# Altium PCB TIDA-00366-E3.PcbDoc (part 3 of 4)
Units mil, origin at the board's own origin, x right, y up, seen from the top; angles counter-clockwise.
Board outline 6298.95 x 6141.73 mil, 4 copper layers (Top Layer, GND, PWR, Bottom Layer), stack 79.834 mil thick; 362 components, 168 nets, 919 pads, 271 vias.
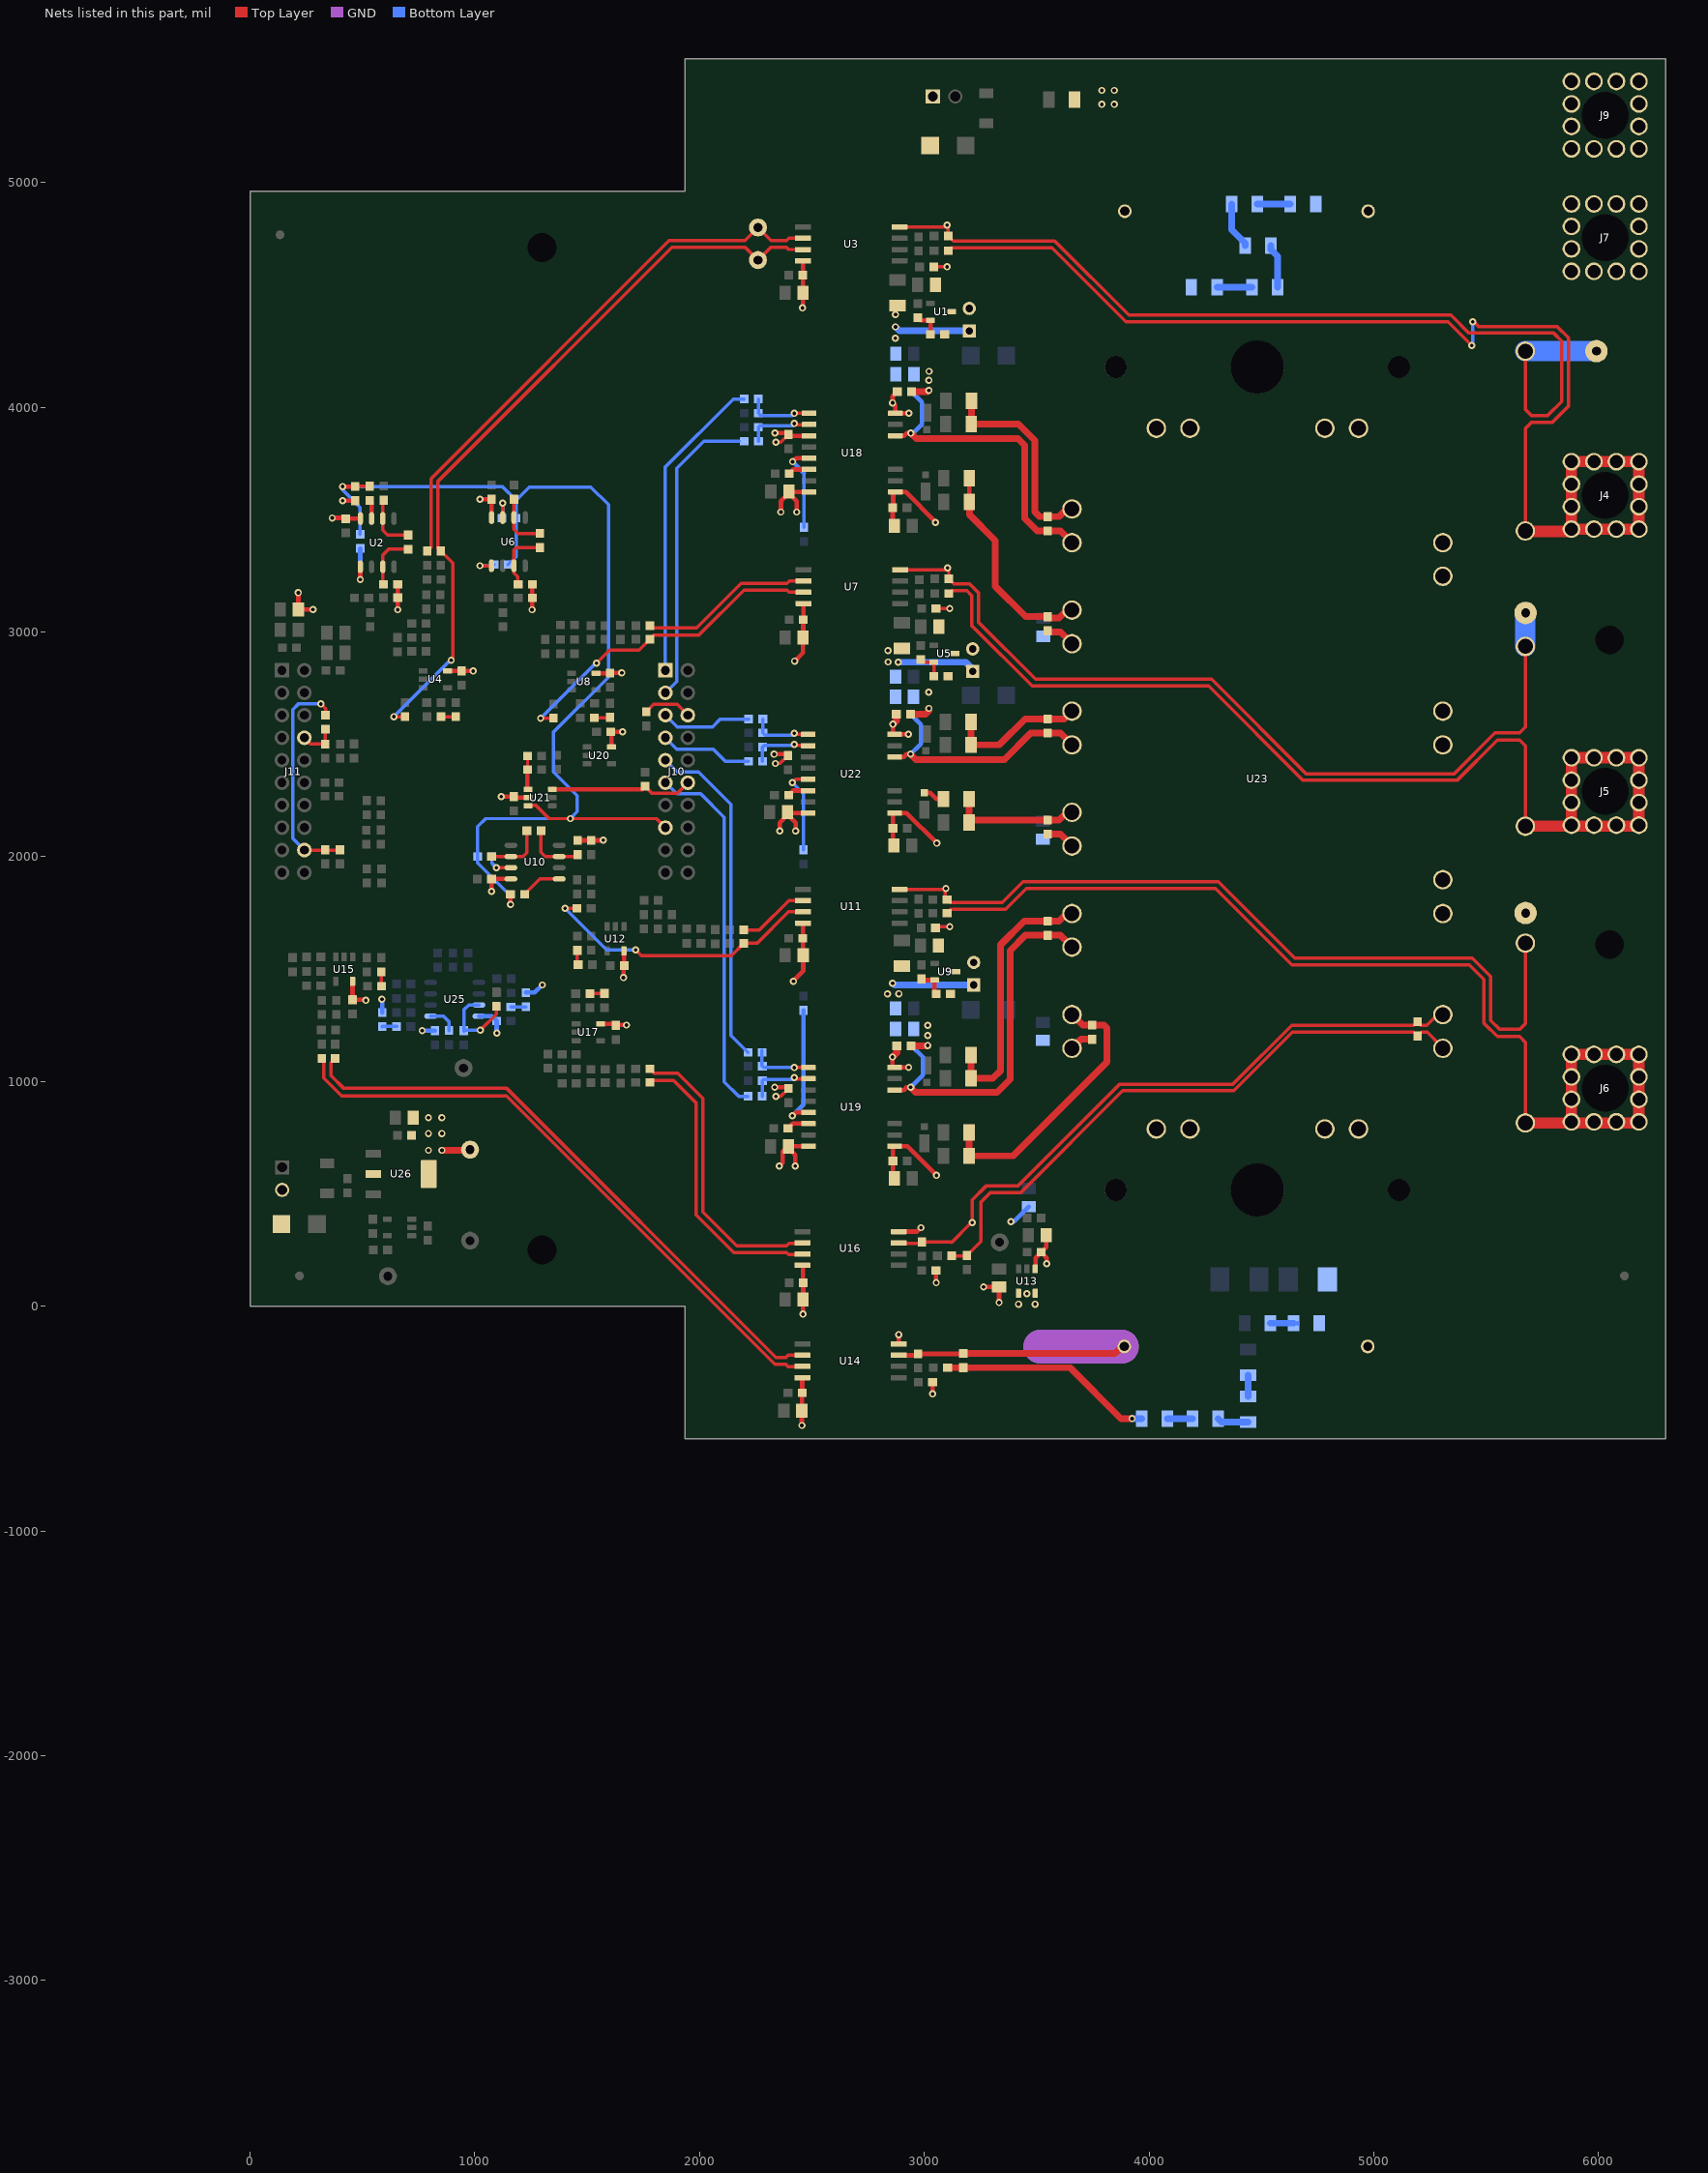
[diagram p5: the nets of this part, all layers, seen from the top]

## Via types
v1: diameter 32, hole 16, Top Layer to Bottom Layer, 271 vias

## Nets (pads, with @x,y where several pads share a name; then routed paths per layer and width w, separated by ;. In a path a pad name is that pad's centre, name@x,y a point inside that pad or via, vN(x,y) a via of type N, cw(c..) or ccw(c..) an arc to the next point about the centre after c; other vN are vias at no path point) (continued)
NetD11_2: D11.2 R130.1 | length 96.4
  Top Layer w20: D11.2@3000,2284.21 3025.79,2284.21 3053.55,2256.45 R130.1@3084.9,2256.45
NetD12_2: D12.2 J8.1
NetD13_2: D13.2 J12.2
NetJ10_1: J10.1 R143.2 | length 1380.6
  Bottom Layer w15: J10.1@1847.73,2829.45 1847.73,3734.45 2149.73,4036.45 R143.2@2198.24,4036.45
NetJ10_3: J10.3 R145.2 | length 1347.9
  Bottom Layer w15: J10.3@1847.73,2729.45 1897.73,2779.45 1897.73,3727.45 2019.28,3848.99 2176.55,3848.99
NetJ10_5: J10.5 R150.2 | length 406.5
  Bottom Layer w15: J10.5@1847.73,2629.45 1899.73,2577.45 2057.73,2577.45 2092.73,2612.45 R150.2@2218.24,2612.45
NetJ10_6: J10.6 R147.2 | length 218.2
  Top Layer w15: R147.2@1763,2644.5 1795.93,2677.43 1899.75,2677.43 J10.6@1947.73,2629.45
NetJ10_7: J10.7 R152.2 | length 413
  Bottom Layer w15: J10.7@1847.73,2529.45 1898.73,2478.45 2060.73,2478.45 2114.73,2424.45 R152.2@2217.24,2424.45
NetJ10_9: J10.9 R153.2 | length 1507.9
  Bottom Layer w15: J10.9@1847.73,2429.45 1899.73,2377.45 1994.73,2377.45 2139.73,2232.45 2139.73,1204.95 R153.2@2215.24,1129.45
NetJ10_11: J10.11 R156.2 | length 1634.5
  Bottom Layer w15: J10.11@1847.73,2329.45 1897.73,2279.45 2004.73,2279.45 2109.73,2174.45 2109.73,997.99 2173.28,934.45 R156.2@2215.24,934.45
NetJ11_8: J11.8 R148.1 R149.1 | length 171.2
  Top Layer w15: J11.8@241.73,2529.45 270.24,2500.95 R148.1@334.73,2500.95 334.73,2565.95 R149.1@335.73,2566.95
NetR2_1: R2.1 R6.2 U1.2 | length 124
  Top Layer w20: R6.2@2970.73,4397.95 2981.64,4387.05 U1.2@3027.49,4387.05 3027.49,4324.7 R2.1@3027.24,4324.45
NetR3_1: R3.1 U2.1 | length 196.5
  Top Layer w20: v1(490.19,3232.82) 490.19,3289.73 U2.1@490.51,3290.06
  Bottom Layer w20: R3.1@490,3371.5 490.51,3370.99 490.19,3370.67 490.19,3290.06 ; v1(490.19,3232.82) 490.51,3233.14 490.51,3290.06
NetR4_1: R4.1 R11.2 U2.3 | length 254.3
  Top Layer w15: R4.1@594.02,3212.34 590.51,3215.84 U2.3@590.51,3290.06 590.51,3341.84 616.59,3367.92 R11.2@703.09,3367.92
NetR7_2: R7.2 R8.1 | length 64.7
  Top Layer w15: R8.1@850.23,2623.45 850.73,2622.95 R7.2@914.73,2622.95
NetR11_1: R11.1 R19.2 U2.6 | length 256.7
  Top Layer w15: R19.2@594.09,3585.92 590.51,3582.35 U2.6@590.51,3504.62 590.51,3451.99 611.59,3430.91 R11.1@703.09,3430.91
NetR15_1: R15.1 TP2.1 U3.6 | length 2475.1
  Top Layer w15: R15.1@788.61,3359.95 804.73,3376.07 804.73,3681.73 1864.45,4741.45 2201.73,4741.45 TP2.1@2259.73,4799.45 2317.73,4741.45 2386.73,4741.45 2396.86,4751.58 U3.6@2460.17,4751.58
NetR20_1: R20.1 U2.7 | length 84.4
  Top Layer w20: R20.1@532,3585.5 540.51,3576.99 U2.7@540.51,3504.62
NetR23_1: R23.1 R27.2 U5.2 | length 125.2
  Top Layer w15: R27.2@2983.73,2876.95 2994.64,2866.05 U5.2@3041.49,2866.05 3042.24,2865.3 R23.1@3042.24,2803.45
NetR24_1: R24.1 U6.1 | length 117.1
  Top Layer w15: v1@1022.95,3294 v1(1022.47,3294.47) U6.1@1074.21,3294.47
  Bottom Layer w15: v1@1022.95,3294 1079.42,3294 R24.1@1085.24,3299.82
NetR25_1: R25.1 R32.2 U6.3 | length 279.7
  Top Layer w15: R25.1@1192.72,3211.76 1190.08,3214.4 1190.08,3246.84 1174.21,3262.7 U6.3@1174.21,3294.47 1174.21,3364.26 1185.21,3375.26 R32.2@1289.21,3375.26
NetR28_2: R28.2 R29.1 | length 69.9
  Top Layer w15: R29.1@1531.76,2618.32 1599.51,2618.32 R28.2@1601.04,2619.84
NetR32_1: R32.1 R40.2 U6.6 | length 256.4
  Top Layer w15: R40.2@1174.21,3590.26 U6.6@1174.21,3509.04 1174.21,3456.41 1192.37,3438.25 R32.1@1289.21,3438.25
NetR36_1: R36.1 U7.6 | length 773.3
  Top Layer w15: R36.1@1779.25,3027.99 1788.79,3018.45 1987.31,3018.45 2185.05,3216.2 2389.08,3216.2 2399.21,3226.32 U7.6@2462.51,3226.32
NetR41_1: R41.1 U6.7 | length 131.5
  Top Layer w15: v1@1124,3573 v1(1124.21,3572.79) U6.7@1124.21,3509.04
  Bottom Layer w15: R41.1@1120.5,3507 1124,3510.5 v1@1124,3573
NetR44_1: R44.1 R48.2 U9.2 | length 125.6
  Top Layer w20: R48.2@2986.73,1455.95 2991.64,1451.05 U9.2@3045.49,1451.05 3045.49,1397.2 R44.1@3053.24,1389.45
NetR45_1: R45.1 U10.1 | length 181.8
  Top Layer w15: R45.1@1221.5,1833 1289.4,1900.91 U10.1@1375.17,1900.91
NetR46_1: R46.1 R53.2 U10.3 | length 270.6
  Top Layer w15: R53.2@1294.38,2115.91 1294.38,2020.48 1313.96,2000.91 U10.3@1375.17,2000.91 1449.38,2000.91 R46.1@1457.88,2009.41
NetR49_2: R49.2 R50.1 | length 65
  Top Layer w15: R50.1@1455.96,1583.41 1455.96,1523.41 R49.2@1459.46,1519.91
NetR53_1: R53.1 R61.2 U10.6 | length 261.8
  Top Layer w15: R61.2@1074.38,2000.91 U10.6@1160.6,2000.91 1213.92,2000.91 1231.39,2018.38 R53.1@1231.39,2115.91
NetR57_1: R57.1 U11.6 | length 317.8
  Top Layer w15: R57.1@2196.23,1674.45 2266.86,1674.45 2396.86,1804.45 U11.6@2460.17,1804.45
NetR62_1: R62.1 U10.7 | length 101.4
  Top Layer w15: v1(1096,1951) 1096.09,1950.91 U10.7@1160.6,1950.91
  Bottom Layer w15: 1075.5,1979.3 1075.5,1971.5 v1(1096,1951)
NetR65_1: R65.1 R66.2 | length 105.2
  Bottom Layer w20: R65.1@4659.73,-75.55 R65.1@4660.73,-76.55
  Bottom Layer w30: R66.2@4538.82,-75.55 R65.1@4642.65,-75.55
NetR68_1: R68.1 R69.2 | length 94.8
  Bottom Layer w30: R69.2@4440.73,-401.46 R68.1@4440.73,-306.63
NetR69_1: R69.1 R70.2 | length 140.2
  Bottom Layer w30: R70.2@4306.82,-500.55 4321.9,-515.63 R69.1@4440.73,-515.63
NetR70_1: R70.1 R73.2 | length 110.8
  Bottom Layer w30: R73.2@4081.82,-500.55 R70.1@4192.65,-500.55
NetR71_2: R71.2 R72.1 | length 64.1
  Top Layer w15: R72.1@583.73,1487.91 583.73,1425.9 R71.2@585.23,1424.4
NetR73_1: R73.1 R74.1 R79.2 | length 958.9
  Top Layer w30: R74.1@3103.23,-273.55 3103.28,-273.5 R79.2@3173,-273.5 3647.68,-273.5 3874.73,-500.55 3875.28,-500 v1(3924,-500)
  Bottom Layer w30: v1(3924,-500) 3967.1,-500 R73.1@3967.65,-500.55
NetR75_1: R75.1 U14.6 | length 2705.8
  Top Layer w15: R75.1@378.73,1102.91 359.93,1084.11 359.93,1026 416.93,969 1142.06,969 2339.73,-228.68 2383.73,-228.68 2393.86,-218.55 U14.6@2457.17,-218.55
NetR80_1: R80.1 U14.7 | length 2752.6
  Top Layer w15: R80.1@318.73,1102.91 328.27,1093.36 328.27,1014.73 408,935 1141.06,935 2334.73,-258.68 2383.73,-258.68 2393.61,-268.55 U14.7@2457.17,-268.55
NetR87_2: R87.2 R88.1 | length 64.7
  Top Layer w15: R88.1@1512.03,1390.91 1576.04,1390.91 R87.2@1576.53,1391.4
NetR90_1: R90.1 U16.6 | length 1307.5
  Top Layer w15: R90.1@1778.28,1055.45 1797.08,1036.65 1902.53,1036.65 2014.73,924.45 2014.73,419.45 2164.86,269.32 2386.73,269.32 2396.86,279.45 U16.6@2460.17,279.45
NetR93_1: R93.1 U16.7 | length 1298.5
  Top Layer w15: R93.1@1778.28,995.45 1787.82,1004.99 1884.19,1004.99 1984.73,904.45 1984.73,407.02 2152.43,239.32 2386.73,239.32 2396.61,229.45 U16.7@2460.17,229.45
NetR102_1: R102.1 R103.2 U21.4 | length 151.2
  Top Layer w12: R102.1@1234.24,2448.23 R103.2@1234.24,2388.23 R103.2@1235.87,2386.6
  Top Layer w20: R103.2@1234.24,2388.23 1234.24,2303.03 U21.4@1236.87,2300.4
NetR110_2: R110.2 U18.5 | length 392.9
  Top Layer w20: v1(2413.73,3757.45) 2429.28,3773 U18.5@2487.07,3773
  Bottom Layer w15: R110.2@2464.73,3465.5 2464.73,3706.45
  Bottom Layer w20: v1(2413.73,3757.45) 2464.73,3706.45
NetR111_2: R111.2 U19.5 | length 571.8
  Top Layer w20: v1(2412.86,846.86) 2429,863 U19.5@2488,863
  Bottom Layer w20: v1(2412.86,846.86) 2462,896 R111.2@2462,1316.5
NetR112_2: R112.2 U18.6 | length 95.5
  Top Layer w20: R112.2@2399.23,3704.45 2417.78,3723 U18.6@2487.07,3723
NetR113_2: R113.2 U19.6 | length 103.8
  Top Layer w20: R113.2@2393.36,790.86 2415.36,812.86 2426.94,812.86 2427.08,813 U19.6@2488,813
NetR127_2: R127.2 U22.5 | length 398.8
  Top Layer w15: v1(2412.73,2329.45) 2427.73,2344.45 U22.5@2485.98,2344.45
  Bottom Layer w15: v1(2412.73,2329.45) 2462,2280.18 R127.2@2462,2030.5
NetR128_2: R128.2 U22.6 | length 98.5
  Top Layer w20: R128.2@2396.23,2273.45 2417.23,2294.45 U22.6@2485.98,2294.45
NetR134_2: R134.2 R135.1 | length 145.8
  Bottom Layer w30: R135.1@4481.82,4904.45 R134.2@4627.65,4904.45
NetR135_2: R135.2 R136.1 | length 209.9
  Bottom Layer w30: R135.2@4367.65,4904.45 4367.65,4789.69 4427.65,4729.69 R136.1@4427.65,4719.45
NetR136_2: R136.2 R137.1 | length 197.4
  Bottom Layer w30: R136.2@4541.82,4719.45 4541.82,4702.36 4571.82,4672.36 R137.1@4571.82,4534.45
NetR137_2: R137.2 R138.1 | length 155.8
  Bottom Layer w30: R138.1@4301.82,4534.45 R137.2@4457.65,4534.45
NetR154_2: R154.2 R155.1 | length 64.7
  Bottom Layer w15: R154.2@587.76,1243.95 588.25,1244.45 R155.1@652.26,1244.45
NetR159_1: R159.1 U25.1 | length 131.2
  Bottom Layer w15: U25.1@803.47,1290.45 860.55,1290.45 885,1266 R159.1@885,1226.5
NetR163_2: R163.2 R165.1 | length 67.7
  Bottom Layer w15: R165.1@1160.23,1331.99 1227.23,1331.99 R163.2@1227.73,1332.5
NetR164_1: R164.1 R167.2 U25.7 | length 382.1
  Top Layer w15: v1(1024,1228) 1095.73,1299.73 R167.2@1095.73,1335.23
  Bottom Layer w15: R164.1@950.73,1225.95 R164.1@952.76,1227.97 ; R164.1@952.76,1222.95 R164.1@952.76,1227.97 ; R164.1@952.79,1228 v1(1024,1228) ; U25.7@1018.04,1340.45 972.76,1340.45 952.76,1320.45 R164.1@952.76,1227.97
NTC: R77.2 R89.1 R129.2 U23.17 | length 2728.1
  Top Layer w15: R89.1@3121.23,224.45 3188.24,224.45 R129.2@3189.73,225.95 3251.23,287.45 3251.23,463.52 3292.16,504.45 3427.73,504.45 3882,958.72 4376.24,958.72 4636.98,1219.45 5177.05,1219.45 R77.2@5194,1202.5 5210.95,1219.45 5236.54,1219.45 U23.17@5295.54,1160.45
OVERLOAD: J10.15 R1.1 R3.2 R20.2 R24.2 R41.2 R45.2 R62.2 U21.6 | length 5019.6
  Top Layer w15: R1.1@468.27,3647.05 469.72,3648.5 R20.2@532,3648.5 ; U21.6@1235.87,2227.6 1272.4,2227.6 1330.55,2169.45 v1(1424.73,2169.45) 1807.73,2169.45 J10.15@1847.73,2129.45
  Top Layer w20: v1(411.76,3647.05) R1.1@468.27,3647.05 ; R45.2@1158.5,1833 1158.5,1787.7 v1(1159,1787.21)
  Bottom Layer w15: R3.2@490,3434.5 490,3554 411.76,3632.24 v1(411.76,3647.05) 1122.95,3647.05 1183.5,3586.5 ; R24.2@1148.23,3299.82 1183.5,3335.09 R41.2@1183.5,3507 1183.5,3586.5 ; v1(1159,1787.21) 1159,1826 1012.5,1972.5 R62.2@1012.5,2001 1012.5,2133.5 1048.45,2169.45 v1(1424.73,2169.45) 1456,2200.72 1456,2271 1350,2377 1350,2554.72 1594.73,2799.45 1594.73,3566.27 1516,3645 1242,3645 1183.5,3586.5
PWM_U_BOT: C96.1 R145.1 U18.2 | length 302.3
  Top Layer w15: v1@2418.61,3932.57 2428.73,3922.45 U18.2@2486.98,3922.45
  Bottom Layer w15: R145.1@2262.23,3848.99 2261.23,3849.99 C96.1@2261.23,3910.99 2268.69,3918.45 2412.73,3918.45 v1(2421.73,3927.45)
PWM_U_TOP: C91.1 R143.1 U18.1 | length 296.3
  Top Layer w15: v1(2421.73,3972.45) U18.1@2486.98,3972.45
  Bottom Layer w15: R143.1@2261.23,4036.45 C91.1@2261.23,3973.99 2271.77,3963.45 2412.73,3963.45 v1(2421.73,3972.45)
PWM_V_BOT: C100.1 R152.1 U22.2 | length 281.2
  Top Layer w15: v1@2417.61,2504.57 2427.73,2494.45 U22.2@2485.98,2494.45
  Bottom Layer w15: R152.1@2280.23,2424.45 C100.1@2280.23,2487.65 2287.03,2494.45 2415.73,2494.45 v1(2420.73,2499.45)
PWM_V_TOP: C99.1 R150.1 U22.1 | length 276.4
  Top Layer w15: v1(2420.73,2549.45) 2425.73,2544.45 U22.1@2485.98,2544.45
  Bottom Layer w15: R150.1@2281.23,2612.45 C99.1@2281.23,2550.99 2291.77,2540.45 2411.73,2540.45 v1(2420.73,2549.45)
PWM_W_BOT: C102.1 R156.1 U19.2 | length 288.9
  Top Layer w15: v1@2417.74,1021.99 2427.86,1011.86 U19.2@2486.11,1011.86
  Bottom Layer w15: R156.1@2278.23,934.45 2278.23,1001.99 C102.1@2279.23,1002.99 2284.69,1008.45 2412.45,1008.45 v1(2420.86,1016.86)
PWM_W_TOP: C101.1 R153.1 U19.1 | length 280.9
  Top Layer w15: v1(2420.86,1061.86) U19.1@2486.11,1061.86
  Bottom Layer w10: C101.1@2278.23,1068.99 C101.1@2279.23,1067.99
  Bottom Layer w15: R153.1@2276.73,1138.45 2276.73,1070.49 C101.1@2278.23,1068.99 ; C101.1@2279.23,1067.99 2285.36,1061.86 v1(2420.86,1061.86)
TRIP: J10.12 R151.2 U21.3 | length 641.1
  Top Layer w15: R151.2@1757.73,2312.95 1789.24,2281.45 1899.73,2281.45 J10.12@1947.73,2329.45
  Top Layer w20: U21.3@1345.13,2300.4 1345.54,2300 1744.78,2300 R151.2@1757.73,2312.95
U_BOT: R114.2 R116.2 R118.2 U23.3 | length 937.6
  Top Layer w20: R118.2@3200.08,3579.45 R114.2@3200.08,3684.45 ; R116.2@3548.73,3067.95 R116.2@3553.73,3062.95
  Top Layer w30: R118.2@3200.08,3579.45 3200.08,3521.92 3315,3407 3315,3203.18 3450.24,3067.95 R116.2@3548.73,3067.95 ; R116.2@3553.73,3062.95 3598.43,3062.95 U23.3@3645.93,3110.45
U_BOT_REF: C72.1 C75.1 R116.1 R133.1 U18.9 U23.4 | length 504.2
  Top Layer w20: C72.1@2859.24,3478.95 C75.1@2859.24,3552.45 2861,3554.21 2861,3622.45 2917.55,3622.45 3050,3490 v1(3050,3487.5)
  Top Layer w30: R116.1@3548.73,2999.95 3606.43,2999.95 U23.4@3645.93,2960.45
U_PHASE: J4.1 R10.1 R121.1 | length 5478.2
  Top Layer w15: R10.1@3106.23,4696.58 3119.23,4709.58 3567.18,4709.58 3897.31,4379.45 5329.73,4379.45 v1(5434.73,4274.45) ; v1(5439.73,4379.45) 5444.73,4379.45 5464.73,4359.45 5814.73,4359.45 5864.73,4309.45 5864.73,4004.45 5791.73,3931.45 5699.73,3931.45 5673.73,3905.45 R121.1@5673.73,3449.45 R121.1@5675.73,3447.45
  Top Layer w50: R121.1@5675.73,3447.45 5868.73,3447.45 J4.1@5878.73,3457.45 ; J4.1@5878.73,3457.45 J4.1@5878.73,3557.45 J4.1@5878.73,3657.45 J4.1@5878.73,3757.45 J4.1@5978.73,3757.45 J4.1@6078.73,3757.45 J4.1@6178.73,3757.45 J4.1@6178.73,3657.45 J4.1@6178.73,3557.45 J4.1@6178.73,3457.45 J4.1@6078.73,3457.45 J4.1@5978.73,3457.45 J4.1@5878.73,3457.45
  Bottom Layer w15: v1(5434.73,4274.45) 5439.73,4279.45 v1(5439.73,4379.45)
U_TOP: R104.2 R106.2 R108.2 U23.1 | length 916.5
  Top Layer w30: R108.2@3209.08,4028.45 3209.08,3925.71 R104.2@3208.82,3925.45 3417.73,3925.45 3491.73,3851.45 3491.73,3534.45 3513.24,3512.95 R106.2@3548.73,3512.95 3598.43,3512.95 U23.1@3645.93,3560.45
U_TOP_REF: C4.1 C5.1 C67.1 C69.1 J2.2 R2.2 R17.1 R106.1 R121.2 TP4.1 U1.3 U3.4 U18.14 U23.2 U23.23 U23.24 | length 5782.7
  Top Layer w15: U3.4@2889.3,4801.58 3091.86,4801.58 v1(3100.73,4810.45) 3106.23,4804.95 R17.1@3106.23,4761.58 3128.23,4739.58 3579.61,4739.58 3909.73,4409.45 5342.16,4409.45 5422.16,4329.45 5799.73,4329.45 5834.73,4294.45 5834.73,4024.45 5773.73,3963.45 5699.73,3963.45 5673.73,3989.45 R121.2@5673.73,4247.45 ; C5.1@3041.23,4624.45 v1(3100.73,4624.45)
  Top Layer w20: U18.14@2861,3872.45 2909.73,3872.45 2921.73,3884.45 v1(2939.73,3884.45)
  Top Layer w30: v1(2939.73,3884.45) 2963.73,3860.45 3415.73,3860.45 3446.73,3829.45 3446.73,3505.45 3502.23,3449.95 R106.1@3548.73,3449.95 3606.43,3449.95 U23.2@3645.93,3410.45 ; C67.1@2942.23,4069.45 3014.45,4069.45 v1(3020,4075)
  Bottom Layer w20: v1(2939.73,3884.45) 2949.73,3884.45 2988.73,3923.45 2988.73,4023.45 2942.73,4069.45 2942.23,4069.45
  Bottom Layer w30: TP4.1@5989.73,4249.45 TP4.1@5994.73,4244.45
  Bottom Layer w90: R121.2@5673.73,4249.45 TP4.1@5989.73,4249.45
  other v1: 3020,4120 3020.73,4159.45
V_BOT: R130.2 R131.2 R132.2 U23.7 | length 576.3
  Top Layer w30: R130.2@3199.08,2256.45 R132.2@3199.08,2151.45 3210.57,2162.95 R131.2@3548.73,2162.95 3598.43,2162.95 U23.7@3645.93,2210.45
V_BOT_REF: C84.1 C85.1 R131.1 R139.1 U22.9 U23.8 | length 513.8
  Top Layer w20: C85.1@2858.24,2124.45 2860,2126.21 2860,2194.45 2920.55,2194.45 v1(3055,2060) ; C85.1@2860.24,2126.45 2860.24,2053.95 C84.1@2864.73,2049.45
  Top Layer w30: R131.1@3548.73,2099.95 3606.43,2099.95 U23.8@3645.93,2060.45
V_DC: C53.1 J11.18 R78.2 R149.2 | length 1004.1
  Top Layer w15: J11.18@241.73,2029.45 R78.2@405.73,2029.45 ; v1(314.73,2679.45) 335.73,2658.45 R149.2@335.73,2629.95
  Bottom Layer w15: J11.18@241.73,2029.45 189.73,2081.45 189.73,2654.45 214.73,2679.45 v1(314.73,2679.45)
V_PHASE: J5.1 R31.1 R123.2 | length 4849.1
  Top Layer w15: R31.1@3108.58,3171.32 3121.58,3184.32 3188.43,3184.32 3209.86,3162.9 3209.86,3029.32 3479.73,2759.45 4264.73,2759.45 4684.73,2339.45 5369.73,2339.45 5549.73,2519.45 5647.73,2519.45 5673.73,2493.45 R123.2@5673.73,2135.45
  Top Layer w50: R123.2@5673.73,2135.45 6173.73,2135.45 J5.1@6178.73,2140.45 J5.1@6178.73,2240.45 J5.1@6178.73,2340.45 J5.1@6178.73,2440.45 J5.1@6078.73,2440.45 J5.1@5978.73,2440.45 J5.1@5878.73,2440.45 J5.1@5878.73,2340.45 J5.1@5878.73,2240.45 J5.1@5878.73,2140.45
V_TOP: R122.2 R125.2 R126.2 U23.5 | length 615.8
  Top Layer w30: R126.2@3208.08,2600.45 3208.08,2497.71 R122.2@3207.82,2497.45 3332.73,2497.45 3448.23,2612.95 R125.2@3548.73,2612.95 3622.43,2612.95 U23.5@3656.93,2647.45 ; U23.5@3644.93,2659.45 U23.5@3645.93,2660.45
V_TOP_REF: C18.1 C19.1 C82.1 C83.1 J3.2 R23.2 R38.1 R123.1 R125.1 TP5.1 U5.3 U7.4 U22.14 U23.6 U23.21 U23.22 | length 5108.5
  Top Layer w15: U7.4@2891.65,3276.32 3094.21,3276.32 v1(3103.08,3285.2) 3108.58,3279.7 R38.1@3108.58,3236.32 3130.58,3214.32 3200.86,3214.32 3239.86,3175.32 3239.86,3044.32 3494.73,2789.45 4277.16,2789.45 4697.16,2369.45 5357.31,2369.45 5539.31,2551.45 5647.73,2551.45 5673.73,2577.45 R123.1@5673.73,2935.45 ; C19.1@3051.23,3104.45 v1(3112.73,3104.45) ; U23.21@5289.73,2510.45 U23.21@5295.54,2510.45
  Top Layer w20: U22.14@2860,2444.45 2908.73,2444.45 2920.73,2456.45 v1(2938.73,2456.45)
  Top Layer w30: C82.1@2938.23,2634.45 3004.45,2634.45 3020,2650 v1(3020,2660) ; v1(2938.73,2456.45) 2962.73,2432.45 3355.73,2432.45 3473.24,2549.95 R125.1@3548.73,2549.95 3606.43,2549.95 U23.6@3645.93,2510.45
  Bottom Layer w20: 2938.23,2634.45 2984.73,2587.95 2984.73,2502.45 v1(2938.73,2456.45)
  Bottom Layer w30: TP5.1@5673.73,3083.45 TP5.1@5674.73,3084.45
  Bottom Layer w90: R123.1@5673.73,2935.45 TP5.1@5673.73,3083.45
  other v1: 3019.73,2731.45
VCC_U: C67.2 C69.2 J2.1 R9.1 R100.1 U18.16 | length 505.7
  Top Layer w20: C67.2@2879.24,4069.45 2858.42,4048.63 2858.73,4048.31 v1(2858.73,4019.45) 2870.93,4007.25 U18.16@2870.93,3973 2930.28,3973 v1(2930.73,3973.45)
  Bottom Layer w30: v1(2871.73,4357.45) 2889.73,4339.45 J2.1@3199.73,4339.45
  other v1: 2870.73,4306.45 2871.73,4412.45
VCC_V: C82.2 C83.2 J3.1 R30.1 R120.1 U22.16 | length 526.2
  Top Layer w20: v1(2860,2589.19) 2860,2544.45 v1(2928.73,2544.45) v1@2931,2542.19
  Top Layer w30: v1(2860,2589.19) 2875.24,2604.43 C82.2@2875.24,2634.45
  Bottom Layer w30: v1(2883.73,2865.45) 3183.73,2865.45 J3.1@3224.73,2824.45
  other v1: 2838.73,2866.45 2837.73,2916.45
VCC_W: C68.2 C70.2 J1.1 R51.1 R101.1 U19.16 | length 539.5
  Top Layer w20: v1(2857.86,1108.86) 2857.86,1064.13 2860.12,1061.86 2928.86,1061.86 v1(2929.86,1062.86)
  Top Layer w30: v1(2857.86,1108.86) 2877.37,1128.37 C68.2@2877.37,1157.86
  Bottom Layer w30: v1(2858.73,1437.45) 2866.73,1429.45 J1.1@3219.73,1429.45
  other v1: 2835.73,1389.45 2886.73,1390.45
VCCI: C1.1 C2.1 C6.2 C7.2 C9.2 C15.1 C16.1 C20.2 C21.2 C23.2 C29.1 C30.1 C34.2 C35.2 C37.2 C48.2 C49.2 C50.2 C59.2 C60.2 C61.2 C74.1 C77.1 C78.1 C79.1 C80.1 C81.1 C86.1 C87.1 C108.1 C109.1 C110.1 R1.2 R4.2 R25.2 R46.2 R146.1 R154.1 R157.2 R163.1 TP9.1 U2.8 U3.8 U4.5 U6.8 U7.8 U8.5 U10.8 U11.8 U12.5 U14.8 U15.5 U16.8 U17.5 U18.3 U18.8 U19.8 U20.5 U21.5 U22.8 U25.8 U26.2 U26.4 | length 4800.2
  Top Layer w15: v1(2336.74,2414.69) 2357.48,2414.69 C86.1@2392.73,2449.95 ; v1(2339.13,933.1) 2359.86,933.1 C80.1@2395.12,968.36 ; v1(2340,3843.69) 2360.73,3843.69 C78.1@2395.99,3878.95
  Top Layer w20: v1(214.73,3174.45) R146.1@214.73,3099.45 v1(279.73,3099.45) ; v1(365.51,3507.34) C1.1@422.01,3507.34 ; v1(411.76,3584.05) R1.2@468.27,3584.05 ; C1.1@425.51,3503.84 426.3,3504.62 U2.8@490.51,3504.62 ; U15.5@456.13,1445.27 C50.2@456.13,1363.5 512.63,1363.5 v1(515.23,1360.9) ; R4.2@657.01,3212.34 657.01,3099.34 v1(657.43,3098.91) ; U4.5@878.87,2826.85 C9.2@940.83,2826.85 991.33,2826.85 v1(992.24,2825.95) ; v1@1020.79,3589.84 1021.21,3590.26 C15.1@1074.21,3590.26 U6.8@1074.21,3509.04 ; v1(1074.38,1845.91) C29.1@1074.38,1900.91 ; C29.1@1074.38,1901.41 C29.1@1074.38,1900.91 ; v1(1117.08,2267.23) C77.1@1173.57,2267.23 1177.8,2263 U21.5@1236.87,2263 ; U10.8@1160.6,1900.91 C29.1@1074.38,1900.91 ; v1(1254.21,3098.77) 1255.71,3100.26 C16.1@1255.71,3151.76 R25.2@1255.71,3211.76 ; R46.2@1457.88,2072.4 C30.1@1517.88,2072.4 1570.41,2072.4 v1(1571.44,2073.43) ; U8.5@1539.2,2816.52 1601.97,2816.52 C23.2@1603.26,2817.81 ; U17.5@1558.87,1256.31 1620.83,1256.31 1624.73,1252.4 1673.24,1252.4 v1(1674.73,1250.91) ; C23.2@1602.36,2818.72 C23.2@1603.26,2817.81 ; U20.5@1608.13,2488.4 1608.13,2551.36 C74.1@1604.5,2555 v1(1657,2555) ; v1(1653.76,2817.81) C23.2@1603.26,2817.81 ; v1(1660.96,1461.91) 1662.45,1463.41 1662.45,1514.91 1663.36,1515.81 U12.5@1663.36,1580.77 ; v1(2331.74,2456) C86.1@2386.68,2456 ; v1(2334.13,974.41) 2389.06,974.41 C80.1@2395.12,968.36 ; v1(2335,3885) C78.1@2389.94,3885 ; v1(2354.61,623.86) 2370,639.26 2370,687.99 C81.1@2389.86,707.85 ; v1(2356.48,2114.46) 2356.48,2151.48 2391.73,2186.73 C87.1@2391.73,2198.45 ; v1(2361.73,3533.45) 2361.73,3582.18 C79.1@2396.99,3617.44 ; C81.1@2389.86,715.86 C81.1@2389.86,707.85 ; C87.1@2391.73,2186.72 2426.99,2151.46 v1(2426.99,2114.46) ; C86.1@2392.73,2449.95 C86.1@2399.23,2443.45 ; C87.1@2395.73,2194.45 U22.8@2483,2194.45 ; C81.1@2395.86,711.86 U19.8@2486.11,711.86 ; C78.1@2395.99,3878.95 2402.49,3872.45 U18.3@2486.98,3872.45 ; C79.1@2396.99,3625.45 C79.1@2396.99,3617.44 ; C79.1@2399.99,3622.45 U18.8@2486.98,3622.45 ; v1(2417.73,1445.45) 2417.73,1448.45 2460.73,1491.45 C34.2@2460.73,1561.45 2459.23,1562.95 C35.2@2459.23,1637.45 2460.17,1638.39 U11.8@2460.17,1704.45 ; v1(2422.73,2870.45) 2459.73,2907.45 C20.2@2459.73,2974.45 2461.23,2975.95 C21.2@2461.23,3054.45 2462.51,3055.73 U7.8@2462.51,3126.32 ; v1(2425.12,623.86) 2425.12,672.6 C81.1@2389.86,707.85 ; v1(2432.24,3533.45) 2432.24,3582.18 C79.1@2396.99,3617.44 ; v1(2454.73,-530.55) C48.2@2454.73,-465.55 2456.23,-464.05 C49.2@2456.23,-385.55 2457,-384.78 U14.8@2457,-318 ; v1(2457.73,4441.45) 2459.73,4443.45 C6.2@2459.73,4509.45 2459.73,4586.95 C7.2@2459.23,4587.45 2460.17,4588.39 U3.8@2460.17,4651.58 ; v1(2459.73,-35.55) C59.2@2459.73,29.45 2461.23,30.95 C60.2@2461.23,104.45 2460.17,105.51 U16.8@2460.17,179.45
  Top Layer w30: v1(853.73,693.45) 975.73,693.45 TP9.1@978.73,696.45
  Bottom Layer w20: v1(586.76,1366.45) 587.76,1365.45 R154.1@587.76,1306.95 ; v1(765.76,1226.45) 765.25,1225.95 R157.2@822.76,1225.95 ; U25.8@1018.04,1290.45 1075.78,1290.45 C110.1@1097.24,1268.99 1097.24,1215.97 v1(1097.76,1215.45) ; R163.1@1227.73,1395.49 1265.77,1395.49 v1(1299.73,1429.45)
  other v1: 793.73,693.45 793.73,768.45 853.73,768.45 793.73,838.45 853.73,838.45 1022.79,3589.84
VDC+: C89.1 C90.1 D1.1 J7.1 R65.2 R134.1 U23.15 U23.16 U23.25 U23.26 | length 2.8
  Top Layer w20: U23.15@4768.73,799.4 U23.15@4770.73,801.4
VDC-: C43.2 C44.2 C45.2 C47.1 C51.2 C58.1 C62.2 C89.2 C90.2 J9.1 R77.1 R79.1 R138.2 R141.2 R142.1 U13.1 U13.4 U13.5 U14.3 U14.4 U16.3 U16.4 U23.13 U23.14 U23.18 U23.27 U23.28 | length 5038.2
  Top Layer w15: U16.3@2889.3,279.45 2983.24,279.45 C62.2@2989.73,285.95 3119.73,285.95 3121.23,284.45 3209.23,372.45 v1(3212.73,372.45) 3212.73,472.88 3274.31,534.45 3415.31,534.45 3868.93,988.07 4373.07,988.07 4634.45,1249.45 5177.95,1249.45 R77.1@5194,1265.5 5210.05,1249.45 5234.54,1249.45 U23.18@5295.54,1310.45
  Top Layer w20: U14.4@2886.13,-168 v1@2886.13,-126.95 ; U16.4@2886.13,332 2967.28,332 v1(2984.73,349.45) v1@2987.18,347 ; U14.3@2886.3,-218.55 2965.24,-218.55 C51.2@2971.73,-212.05 3171.45,-212.05 R79.1@3173,-210.5 ; C47.1@3036.23,-338.55 3036.23,-390.05 v1(3036.73,-390.55) ; C58.1@3051.23,159.45 3051.23,105.95 v1(3052.73,104.45) ; v1(3263.33,85.32) C45.2@3332.33,85.32 ; v1(3332.33,16.32) C45.2@3332.33,85.32 ; C45.2@3346.47,99.45 C45.2@3332.33,85.32 ; U13.1@3494.73,166.13 3494.73,215.22 C44.2@3519.83,240.32 ; C43.2@3542.33,316.32 3542.33,262.82 C44.2@3519.83,240.32 ; v1(3544.73,189.45) 3544.73,215.41 C44.2@3519.83,240.32
  Top Layer w30: v1(2885.73,-126.55) v1@2886.13,-126.95 ; R79.1@3173,-210.5 3848.78,-210.5 C89.2@3879.73,-179.55
  GND w150: 3514.73,-179.55 C89.2@3879.73,-179.55
  Bottom Layer w20: v1@3383.73,377.45 v1(3384.73,376.45) 3397.73,376.45 R142.1@3464.73,443.45
  other v1: 3418.6,9 3493,9 3456,55.99 3789.73,5347.45 3844.73,5347.45 3789.73,5409.45 3844.73,5409.45
VOUTP_U: R12.1 R18.1 TP1.1 U3.7 | length 3342.6
  Top Layer w15: v1(639.25,2623.22) R18.1@688.75,2623.22 ; v1(894.73,2874.45) 901.73,2881.45 901.73,3306.82 R12.1@848.61,3359.95 834.73,3373.82 834.73,3668.73 1877.45,4711.45 2202.73,4711.45 TP1.1@2259.73,4654.45 2316.73,4711.45 2386.73,4711.45 2396.61,4701.58 U3.7@2460.17,4701.58
  Bottom Layer w15: v1(639.25,2623.22) 890.48,2874.45 v1(894.73,2874.45)
VOUTP_V: R33.1 R39.1 U7.7 | length 1466.6
  Top Layer w15: v1(1292.85,2616.36) R39.1@1349.68,2616.36 ; v1(1541.53,2861.59) 1599.39,2919.45 1730.7,2919.45 R33.1@1779.25,2967.99 1798.05,2986.79 1998.08,2986.79 2197.48,3186.2 2389.08,3186.2 2398.95,3176.32 U7.7@2462.51,3176.32
  Bottom Layer w15: v1(1292.85,2616.36) 1538.08,2861.59 v1(1541.53,2861.59)
VOUTP_W: R54.1 R60.1 U11.7 | length 1280.7
  Top Layer w15: v1(1400.96,1769.91) R60.1@1454.46,1769.91 ; v1(1715.96,1584.91) 1741.41,1559.45 2141.23,1559.45 R54.1@2196.23,1614.45 2254.73,1614.45 2394.73,1754.45 U11.7@2460.17,1754.45
  Bottom Layer w15: v1(1400.96,1769.91) 1585.96,1584.91 v1(1715.96,1584.91)
W_BOT: R115.2 R117.2 R119.2 U23.11 | length 1222.5
  Top Layer w30: R115.2@3199.2,773.86 R119.2@3199.2,668.86 3394.86,668.86 3813,1087 3813,1236 3798.5,1250.5 R117.2@3746,1250.5 3703.88,1250.5 U23.11@3656.93,1297.45
W_BOT_REF: C73.1 C76.1 R117.1 R140.1 U19.9 U23.12 | length 498.4
  Top Layer w20: C73.1@2865.86,568.86 2860.37,574.36 C76.1@2860.37,645.86 2860.12,646.1 2860.12,711.86 2923.86,711.86 v1(3053.73,581.99)
  Top Layer w30: U23.12@3656.93,1147.45 3696.98,1187.5 R117.1@3746,1187.5
W_PHASE: J6.1 R52.1 R124.2 | length 4780.7
  Top Layer w15: R52.1@3101.23,1749.45 3117.23,1765.45 3360.73,1765.45 3453.73,1858.45 4295.73,1858.45 4634.73,1519.45 5424.73,1519.45 5489.73,1454.45 5489.73,1259.45 5549.73,1199.45 5647.73,1199.45 5673.73,1173.45 R124.2@5673.73,815.45
  Top Layer w50: R124.2@5673.73,815.45 6173.73,815.45 J6.1@6178.73,820.45 J6.1@6178.73,920.45 J6.1@6178.73,1020.45 J6.1@6178.73,1120.45 J6.1@6078.73,1120.45 J6.1@5978.73,1120.45 J6.1@5878.73,1120.45 J6.1@5878.73,1020.45 J6.1@5878.73,920.45 J6.1@5878.73,820.45
W_TOP: R105.2 R107.2 R109.2 U23.9 | length 1177.7
  Top Layer w30: R109.2@3208.2,1117.86 3208.2,1015.12 R105.2@3207.95,1014.86 3305.15,1014.86 3339.73,1049.45 3339.73,1608.95 3443.73,1712.95 R107.2@3548.73,1712.95 3598.43,1712.95 U23.9@3645.93,1760.45
W_TOP_REF: C32.1 C33.1 C68.1 C70.1 J1.2 R44.2 R59.1 R107.1 R124.1 TP6.1 U9.3 U11.4 U19.14 U23.10 U23.19 U23.20 | length 5431.6
  Top Layer w15: U11.4@2889.3,1854.45 v1@3091.86,1854.45 ; C33.1@3049.23,1683.45 C33.1@3054.23,1688.45 ; 3071.91,1688.45 v1(3112.73,1688.45) ; v1@3101.23,1852.83 v1(3095.73,1858.32) v1@3091.86,1854.45 ; U23.20@5294.54,1909.45 U23.20@5295.54,1910.45 ; R124.1@5673.73,1615.45 5673.73,1257.45 5647.73,1231.45 5560.16,1231.45 5519.73,1271.88 5519.73,1466.88 5437.16,1549.45 4647.16,1549.45 4308.16,1888.45 3438.73,1888.45 3345.73,1795.45 3115.23,1795.45 R59.1@3101.23,1809.45 3091.86,1818.82 v1@3091.86,1854.45
  Top Layer w20: U19.14@2860.12,961.86 2908.86,961.86 2920.86,973.86 v1(2938.86,973.86)
  Top Layer w30: v1(2938.86,973.86) 2960.27,952.45 3323.73,952.45 3381.73,1010.45 3381.73,1582.45 3449.24,1649.95 R107.1@3548.73,1649.95 3606.43,1649.95 U23.10@3645.93,1610.45 ; C68.1@2940.36,1157.86 3012.86,1157.86 v1(3015,1160)
  Bottom Layer w20: v1(2938.86,973.86) 2992.86,1027.86 2992.86,1108.86 2943.86,1157.86 2940.36,1157.86
  other v1: 3015,1205 3015,1250
pads on no net: FID1.1 FID2.1 FID3.1 FID4.1 FID5.1 FID6.1 H1.1 H2.1 H3.1 H4.1 H5.0 H6.0 H7.0 H8.0 J4. J5. J6. J7. J9. J10.4 J10.8 J10.10 J10.14 J10.16 J10.17 J10.19 J10.20 J11.3 J11.5 J11.6 J11.7 J11.9 J11.13 J11.15 J11.17 J11.20 LBL1.0 U18.7 U19.3 U19.7 U22.3 U22.7 U23.MH1 U23.MH2 U23.MH3 U23.MH4 U23.MH5 U23.MH6

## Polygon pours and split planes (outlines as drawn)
VDC- on Top Layer "VDC-_L01_P139" (solid, remove dead copper, pour order 139): 3385.13,130 3378.4,123.27 3237.27,123.27 3204,90 3204,-137 3216,-149 3531,-149 3559.73,-120.27 3559.73,349.27 3552.68,356.32 3522.24,356.32 3512.93,347 3512.93,273.93 3498,259 3498,229.45 3481,212.45 3481,135.84 3475.16,130
V_TOP_REF on Top Layer "PWR-No Net" (solid, remove dead copper, pour order 127): 3034.73,3077.45 3034.73,2982.45 3036.34,2980.84 3071.18,2980.84 3080.15,2971.87 3085.73,2966.29 3085.73,2943.45 3085.73,2771.45 3066.73,2752.45 3002.73,2752.45 2984.73,2734.45 2984.73,2615.27 2995,2605 3035,2605 3044.73,2614.73 3044.73,2673.45 3050.73,2679.45 3147.73,2679.45 3161.73,2693.45 3161.73,3122.45 3154.73,3129.45 3039.73,3129.45 3034.73,3124.45
W_TOP_REF on Top Layer "Top Layer-No Net 1" (solid, remove dead copper, pour order 109): 3030.73,1711.45 3030.73,1574.45 3034.73,1570.45 3084.73,1570.45 3092.73,1562.45 3092.73,1358.45 2989.73,1255.45 2989.73,1145.27 3000,1135 3035,1135 3044.73,1144.73 3044.73,1224.45 3165.73,1345.45 3165.73,1712.45 3157.73,1720.45 3032.73,1720.45 3030.73,1718.45
NetC4_2 on Top Layer "Top Layer-No Net 1" (solid, remove dead copper, pour order 108): 3000.73,4655.45 2944.73,4655.45 2929.73,4670.45 2846.73,4670.45 2841.73,4665.45 2841.73,4521.45 2842.73,4522.45 2912.73,4522.45 2927.73,4522.45 2936.73,4513.45 2942.19,4507.99 2942.19,4448.45 2942.19,4438.99 2945.73,4435.45 3046.73,4435.45 3051.73,4440.45 3051.73,4477.5 3045.73,4483.5 3006.25,4483.5 3002.73,4487.02 3002.73,4636.45 3002.73,4653.45 3000.73,4655.45
U_TOP_REF on Top Layer "Top Layer-No Net 1" (solid, remove dead copper, pour order 110): 3018.73,4647.45 3018.73,4510.45 3022.73,4506.45 3049.73,4506.45 3067.73,4488.45 3067.73,4238.45 3000.73,4171.45 2977.73,4148.45 2977.73,4057.27 2985,4050 3030,4050 3039.73,4059.73 3039.73,4129.45 3153.73,4243.45 3153.73,4305.45 3153.73,4648.45 3145.73,4656.45 3020.73,4656.45 3018.73,4654.45
VCC_U on Top Layer "Top Layer-No Net 1" (solid, remove dead copper, pour order 112): 2834.73,4499.45 2915.73,4499.45 2919.73,4495.45 2919.73,4294.45 2909.73,4284.45 2839.73,4284.45 2832.73,4291.45 2832.73,4497.45
NetC18_2 on Top Layer "Top Layer-No Net 1" (solid, remove dead copper, pour order 114): 3009.73,3132.99 2938.19,3132.99 2931.73,3139.45 2926.73,3144.45 2865.73,3144.45 2853.73,3144.45 2850.73,3141.45 2850.73,2999.45 2857.73,2992.45 2940.73,2992.45 2949.73,2983.45 2956.53,2976.65 2956.53,2942.45 2956.53,2918.65 2961.73,2913.45 3060.73,2913.45 3065.73,2918.45 3065.73,2957.45 3062.73,2960.45 3025.79,2960.45 3023.73,2962.5 3012.73,2973.5 3012.73,3029.45 3012.73,3129.99 3009.73,3132.99
VCC_V on Top Layer "Top Layer-No Net 1" (solid, remove dead copper, pour order 115): 2937.73,2977.45 2830.73,2977.45 2824.73,2971.45 2819.73,2966.45 2819.73,2898.45 2819.73,2843.45 2823.73,2839.45 2930.73,2839.45 2939.73,2848.45 2939.73,2976.45 2938.73,2977.45
VCC_W on Top Layer "Top Layer-No Net 1" (solid, remove dead copper, pour order 117): 2859.73,1560.45 2938.73,1560.45 2940.73,1558.45 2940.73,1372.45 2934.73,1366.45 2823.73,1366.45 2818.73,1371.45 2818.73,1554.45 2824.73,1560.45
NetC32_2 on Top Layer "Top Layer-No Net 1" (solid, remove dead copper, pour order 118): 3009.73,1612.45 3009.73,1706.45 3007.73,1708.45 2945.73,1708.45 2932.73,1721.45 2911.73,1721.45 2850.73,1721.45 2848.73,1719.45 2848.73,1584.45 2851.73,1581.45 2943.73,1581.45 2954.73,1570.45 2959.53,1565.65 2959.53,1521.45 2959.53,1498.65 2963.73,1494.45 3065.73,1494.45 3069.73,1498.45 3069.73,1542.45 3066.73,1545.45 3015.98,1545.45 3014,1547.43 3009.73,1551.7 3009.73,1605.45
+16V_GPS on Top Layer "Top Layer-No Net 1" (solid, remove dead copper, pour order 102): 3344.73,5294.45 3109.73,5294.45 3104.73,5289.45 3104.73,5089.45 3109.73,5084.45 3558.73,5084.45 3576.73,5102.45 3576.73,5286.45 3568.73,5294.45
NetD12_2 on Top Layer "Top Layer-No Net 1" (solid, remove dead copper, pour order 103): 3074.73,5429.45 3074.73,5109.45 3069.73,5104.45 2984.73,5104.45 2979.73,5109.45 2973.76,5115.43 2973.76,5324.45 2973.76,5428.47 2979.73,5434.45 3069.73,5434.45 3074.73,5429.45
VDC- on Top Layer "Top Layer-No Net 1" (solid, remove dead copper, pour order 83): 3648.73,5319.45 3736.73,5319.45 3879.73,5319.45 3884.73,5324.45 3884.73,5429.45 3874.73,5439.45 3648.73,5439.45 3639.73,5430.45 3639.73,5328.45
GND1 on Top Layer "Top Layer-No Net 1" (solid, remove dead copper, pour order 74): 3110.73,5315.45 3570.73,5315.45 3579.73,5324.45 3579.73,5449.45 3568.73,5460.45 3109.73,5460.45 3102.73,5453.45 3102.73,5323.45
W_PHASE on Top Layer "Top Layer-No Net 1" (solid, remove dead copper, pour order 101): 6214.73,1179.45 5797.73,1179.45 5787.73,1169.45 5787.73,879.45 5779.73,871.45 5595.73,871.45 5579.25,854.96 5579.25,769.94 5592.73,756.45 6211.73,756.45 6234.73,779.45 6234.73,1160.45 6214.73,1180.45
V_PHASE on Top Layer "Top Layer-No Net 1" (solid, remove dead copper, pour order 93): 6214.73,2499.45 5797.73,2499.45 5787.73,2489.45 5787.73,2199.45 5779.73,2191.45 5595.73,2191.45 5579.25,2174.96 5579.25,2089.94 5592.73,2076.45 6211.73,2076.45 6234.73,2099.45 6234.73,2480.45 6214.73,2500.45
U_PHASE on Top Layer "Top Layer-No Net 1" (solid, remove dead copper, pour order 97): 6214.73,3811.45 5797.73,3811.45 5787.73,3801.45 5787.73,3511.45 5779.73,3503.45 5595.73,3503.45 5579.25,3486.96 5579.25,3401.94 5592.73,3388.45 6211.73,3388.45 6234.73,3411.45 6234.73,3792.45 6214.73,3812.45
U_TOP_REF on Top Layer "Top Layer-No Net 1" (solid, remove dead copper, pour order 82): 5754.73,4304.45 5768.22,4290.96 5768.22,4259.45 5768.22,4202.94 5754.73,4189.45 5564.73,4189.45 5479.73,4104.45 5371.5,3996.21 5371.5,3594.45 5371.5,3201.21 5359.73,3189.45 5254.73,3189.45 5249.73,3194.45 5249.73,4029.45 5519.73,4299.45 5524.73,4304.45 5754.73,4304.45
V_TOP_REF on Top Layer "Top Layer-No Net 1" (solid, remove dead copper, pour order 78): 5254.73,2689.45 5254.73,2459.45 5264.73,2449.45 5361.5,2449.45 5371.5,2459.45 5371.5,2866.21 5389.73,2884.45 5759.73,2884.45 5764.73,2889.45 5764.73,2984.45 5749.73,2999.45 5269.73,2999.45 5254.73,2984.45
W_TOP_REF on Top Layer "Top Layer-No Net 1" (solid, remove dead copper, pour order 73): 5239.73,1944.45 5239.73,1714.45 5259.73,1694.45 5569.73,1694.45 5579.73,1684.45 5579.73,1584.45 5589.73,1574.45 5753.22,1574.45 5768.22,1589.45 5768.22,1740.96 5749.73,1759.45 5724.73,1784.45 5384.73,1784.45 5371.5,1797.69 5371.5,1799.45 5371.5,1937.69 5359.73,1949.45 5244.73,1949.45 5239.73,1944.45
NetD13_2 on Top Layer "Top Layer-No Net 1" (solid, remove dead copper, pour order 119): 183.73,553.45 98.73,553.45 93.73,548.45 93.73,313.45 93.73,308.45 98.73,303.45 188.73,303.45 193.73,308.45 193.73,543.45
GND on Top Layer "Top Layer-No Net 1" (solid, remove dead copper, pour order 107): 488.73,781.45 488.73,656.45 493.73,651.45 663.73,651.45 673.73,661.45 678.73,666.45 678.73,798.45 678.73,876.45 673.73,881.45 498.73,881.45 488.73,871.45
VCCI on Top Layer "Top Layer-No Net 1" (solid, remove dead copper, pour order 120): 698.73,878.45 698.73,633.45 683.73,618.45 518.73,618.45 508.73,608.45 508.73,563.45 513.73,558.45 678.73,558.45 688.73,548.45 693.73,543.45 698.73,538.45 698.73,503.45 698.73,475.5 713.73,460.5 870.78,460.5 878.73,468.45 878.73,878.45 868.73,888.45 703.73,888.45 698.73,883.45
5V0 on Top Layer "Top Layer-No Net 1" (solid, remove dead copper, pour order 123): 243.73,336.45 243.73,306.45 248.73,301.45 363.73,301.45 363.73,361.45 368.73,366.45 593.82,366.45 605.38,378.01 605.38,514.8 593.73,526.45 248.73,526.45 243.73,521.45
GND on Top Layer "Top Layer-No Net 1" (solid, remove dead copper, pour order 111): 108.73,576.45 358.73,576.45 393.73,541.45 457.28,541.45 462.28,546.45 462.28,712.91 453.73,721.45 443.73,731.45 228.73,731.45 103.73,731.45 98.73,726.45 93.73,721.45 93.73,581.45 98.73,576.45
VDC- on Bottom Layer "Top Layer-No Net 1" (solid, remove dead copper, pour order 143): 2822.51,421.93 2822.51,-533.07 2842.51,-553.07 3542.51,-553.07 3557.51,-538.07 3557.51,401.93 3537.51,421.93 3525.24,434.2 2834.77,434.2
V_BOT_REF on Bottom Layer "Top Layer-No Net 1" (solid, remove dead copper, pour order 138): 3152.73,2308.45 3443.73,2308.45 3453.73,2298.45 3453.73,2121.45 3464.73,2110.45 3685.73,2110.45 3694.73,2101.45 3694.73,2016.45 3687.73,2009.45 2830.73,2009.45 2819.73,2020.45 2819.73,2301.54 2826.65,2308.45 3152.73,2308.45
U_BOT_REF on Bottom Layer "Top Layer-No Net 1" (solid, remove dead copper, pour order 137): 3618.73,3004.45 3689.73,3004.45 3697.73,2996.45 3697.73,2919.45 3682.73,2904.45 3483.73,2904.45 3297.73,3090.45 3297.73,3396.45 3261.73,3432.45 2831.73,3432.45 2820.73,3443.45 2820.73,3729.45 2825.73,3734.45 3324.73,3734.45 3380.73,3678.45 3380.73,3218.45 3479.73,3119.45 3479.73,3021.45 3496.23,3004.95
W_BOT_REF on Bottom Layer "Top Layer-No Net 1" (solid, remove dead copper, pour order 135): 3501.73,1215.45 3690.73,1215.45 3695.73,1210.45 3695.73,1123.45 3687.73,1115.45 3585.73,1115.45 3577.73,1107.45 3577.73,552.45 3553.73,528.45 3478.73,528.45 2832.27,528.45 2819.86,540.86 2819.86,822.45 2823.86,826.45 3425.73,826.45 3444.73,845.45 3444.73,1203.45 3455.73,1214.45 3456.73,1215.45 3494.73,1215.45
W_TOP_REF on Bottom Layer "PWR-No Net" (solid, remove dead copper, pour order 121): 2914.86,949.86 3042.86,949.86 3046.86,953.86 3046.86,1261.86 3037.86,1270.86 2931.25,1270.86 2922.25,1261.86 2922.25,1137.11 2969.7,1089.67 2969.7,1036.7 2925.86,992.86 2911.78,978.78 2911.78,958.23 2911.78,952.94 2914.86,949.86
V_TOP_REF on Bottom Layer "PWR-No Net" (solid, remove dead copper, pour order 122): 2914.73,2432.45 3042.73,2432.45 3046.73,2436.45 3046.73,2744.45 3037.73,2753.45 2931.12,2753.45 2922.13,2744.45 2922.13,2619.7 2969.57,2572.25 2969.57,2519.29 2925.73,2475.45 2911.65,2461.37 2911.65,2440.82 2911.65,2435.53 2914.73,2432.45
U_TOP_REF on Bottom Layer "PWR-No Net" (solid, remove dead copper, pour order 124): 2915.73,3860.45 3043.73,3860.45 3047.73,3864.45 3047.73,4172.45 3038.73,4181.45 2932.12,4181.45 2923.13,4172.45 2923.13,4047.7 2970.57,4000.25 2970.57,3947.29 2926.73,3903.45 2912.65,3889.37 2912.65,3868.82 2912.65,3863.53 2915.73,3860.45
VCC_V on Bottom Layer "Top Layer-No Net 1" (solid, remove dead copper, pour order 104): 2824.73,2937.45 2820,2932.71 2820,2530.19 2828,2522.19 2945,2522.19 2953,2530.19 2953,2562.19 2911,2604.19 2904,2611.19 2904,2658.19 2904,2923.19 2889.73,2937.45
VCC_U on Bottom Layer "Top Layer-No Net 1" (solid, remove dead copper, pour order 113): 2827.73,3952.45 2943.73,3952.45 2951.73,3960.45 2951.73,3992.45 2942.73,4001.45 2902.73,4041.45 2902.73,4231.45 2902.73,4430.45 2890.73,4442.45 2830.73,4442.45 2818.73,4430.45 2818.73,3960.45 2826.73,3952.45
VCC_W on Bottom Layer "Top Layer-No Net 1" (solid, remove dead copper, pour order 116): 2825.73,1041.45 2943.73,1041.45 2950.73,1048.45 2950.73,1076.45 2901.73,1125.45 2901.73,1177.45 2901.73,1446.45 2893.73,1454.45 2827.73,1454.45 2818.73,1445.45 2818.73,1048.45
W_PHASE on Bottom Layer "Top Layer-No Net 1" (solid, remove dead copper, pour order 98): 6214.73,1179.45 5797.73,1179.45 5787.73,1169.45 5787.73,879.45 5779.73,871.45 5595.73,871.45 5579.25,854.96 5579.25,769.94 5592.73,756.45 6211.73,756.45 6234.73,779.45 6234.73,1160.45 6214.73,1180.45
V_PHASE on Bottom Layer "Top Layer-No Net 1" (solid, remove dead copper, pour order 87): 6214.73,2499.45 5797.73,2499.45 5787.73,2489.45 5787.73,2199.45 5779.73,2191.45 5595.73,2191.45 5579.25,2174.96 5579.25,2089.94 5592.73,2076.45 6211.73,2076.45 6234.73,2099.45 6234.73,2480.45 6214.73,2500.45
U_PHASE on Bottom Layer "Top Layer-No Net 1" (solid, remove dead copper, pour order 94): 6214.73,3811.45 5797.73,3811.45 5787.73,3801.45 5787.73,3511.45 5779.73,3503.45 5595.73,3503.45 5579.25,3486.96 5579.25,3401.94 5592.73,3388.45 6211.73,3388.45 6234.73,3411.45 6234.73,3792.45 6214.73,3812.45
W_TOP_REF on Bottom Layer "Top Layer-No Net 1" (solid, remove dead copper, pour order 72): 5239.73,1944.45 5239.73,1714.45 5259.73,1694.45 5569.73,1694.45 5579.73,1684.45 5579.73,1584.45 5589.73,1574.45 5753.22,1574.45 5768.22,1589.45 5768.22,1740.96 5749.73,1759.45 5724.73,1784.45 5384.73,1784.45 5371.5,1797.69 5371.5,1799.45 5371.5,1937.69 5359.73,1949.45 5244.73,1949.45 5239.73,1944.45
V_TOP_REF on Bottom Layer "Top Layer-No Net 1" (solid, remove dead copper, pour order 77): 5254.73,2689.45 5254.73,2459.45 5264.73,2449.45 5361.5,2449.45 5371.5,2459.45 5371.5,2866.21 5389.73,2884.45 5759.73,2884.45 5764.73,2889.45 5764.73,2984.45 5749.73,2999.45 5269.73,2999.45 5254.73,2984.45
